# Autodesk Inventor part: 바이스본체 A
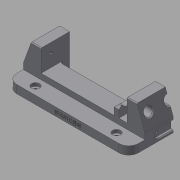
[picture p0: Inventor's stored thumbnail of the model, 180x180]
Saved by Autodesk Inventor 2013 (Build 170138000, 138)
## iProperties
Created: 2017-04
Part Number: 바이스본체 A
Material: 일반
Document SubType Name: Modeling
Designer: mduedu
Density: 1 g/cm^3
Mass: 119.631 g
Surface Area: 276.734 cm^2
Volume: 119.631 cm^3
Author: mduedu
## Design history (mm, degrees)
sketch "스케치1"
  geometry: L1 (-75, 0)-(75, 0); L2 (-75, 0)-(-75, 17); L3 (-53, 17)-(53, 17); L4 (75, 17)-(75, 0); L5 (-75, 17)-(-65.173, 44); L6 (-65.173, 44)-(-53, 44); L7 (-53, 44)-(-53, 17); L8 (0, 0)-(0, 17); L9 (75, 17)-(65.173, 44); L10 (65.173, 44)-(53, 44); L11 (53, 44)-(53, 17); 1 further point
  constraints: 22 end point, 4 perpendicular, 2 horizontal alignment, 2 midpoint, 2 symmetric about line, 1 coincident, 1 collinear, 1 horizontal, 1 vertical
  dimensions: "d0" = 150 distance of L1.start L1.end; "d1" = 17 distance of L1.start L2.end; "d2" = 27 distance of L3.start L6.end; "d3" = 22 distance of L3.start L2.end; "d4" = 70 deg angle of L3 L5; "d54" = 20 deg angle of L9 L4
extrude "돌출1" new body sketch "스케치1" stored distance "d5" = 70; taper "d6" = 0 deg
sketch "스케치2"
  geometry: L1 (0, 70)-(106, 70) reference; L2 (106, 70)-(106, 0) reference; L3 (106, 0)-(0, 0) reference; L4 (0, 47)-(106, 47); L5 (106, 47)-(106, 23); L6 (106, 23)-(0, 23); L7 (0, 23)-(0, 47); L8 (0, 70)-(0, 0) reference; 2 further points
  constraints: 8 end point, 2 parallel, 2 point on line, 1 horizontal, 1 horizontal alignment, 1 midpoint, 1 perpendicular
  dimensions: "d7" = 24 distance between parallel lines of L6 L4
extrude "돌출2" cut sketch "스케치2" stored distance "d9" = 70; taper "d10" = 0 deg
sketch "스케치3"
  geometry: L1 (22, -23)-(128, -23) reference; L2 (128, -47)-(22, -47) reference; L3 (22, -18)-(128, -18); L4 (128, -52)-(22, -52); L5 (22, -18)-(22, -52); L6 (128, -18)-(128, -52); 1 further point
  constraints: 8 end point, 3 parallel, 2 point on line, 1 perpendicular
  dimensions: "d11" = 5 distance between parallel lines of L3 L1; "d12" = 5 distance between parallel lines of L4 L2
extrude "돌출3" cut sketch "스케치3" distance "d13" = 12; taper "d14" = 0 deg
fillet "모깎기1" dims "d15" = 3, "d16" = 3
sketch "스케치4"
  geometry: L1 (103, 23)-(3, 23) reference; L2 (0, 26)-(0, 0) reference; L3 (106, 0)-(0, 0) reference; L4 (106, 26)-(106, 0) reference; L5 (96, 0)-(90, 0); L6 (90, 0)-(90, 19.5); L7 (96, 19.5)-(96, 0); L8 (90, 19.5)-(96, 19.5); A1 r 3 centre (3, 26) between (0, 26) and (3, 23) reference; A2 r 3 centre (103, 26) between (103, 23) and (106, 26) reference; 1 further point
  constraints: 8 end point, 2 perpendicular, 1 horizontal, 1 parallel, 1 point on line
  dimensions: "d17" = 10 distance between parallel lines of L7 L4; "d18" = 6 distance between parallel lines of L7 L6; "d27" = 3.5 distance between parallel lines of L8 L1
extrude "돌출4" join sketch "스케치4" distance "d19" = 12; taper "d20" = 0 deg
chamfer "모따기1" distance "d21" = 3; stored, may be unused: second distance "d22" = 2, angle "d23" = 45 deg
chamfer "모따기2" distance "d24" = 3; stored, may be unused: second distance "d25" = 2, angle "d26" = 45 deg
sketch "스케치5"
  geometry: L1 (-15.5, 35.8)-(-15.5, -25.8) reference; L2 (19.5, 0)-(0, 0) reference; C1 r 6.5 at (9.5, 15); 1 further point
  constraints: 1 centre point
  dimensions: "d28" = 13 diameter of C1; "d30" = 15 distance from line of C1.centre L2; "d31" = 25 distance from line of C1.centre L1
extrude "돌출5" cut sketch "스케치5" stored distance "d32" = 12; taper "d33" = 0 deg
sketch "스케치6"
  geometry: C1 r 5 at (-10, 15); C2 r 5 at (-60, 15); A1 r 6.5 centre (-10, 15) between (-15.766, 12) and (-4.234, 12) reference; A2 r 6.5 centre (-60, 15) between (-65.766, 12) and (-54.234, 12) reference; 1 further point
  constraints: 2 centre point, 2 coincident
  dimensions: "d34" = 10 diameter of C1; "d35" = 10 diameter of C2 (= d34)
extrude "돌출6" cut sketch "스케치6" stored distance "d36" = 12; taper "d37" = 0 deg
chamfer "모따기3" distance "d38" = 1; stored, may be unused: second distance "d39" = 2, angle "d40" = 45 deg
chamfer "모따기4" distance "d41" = 1; stored, may be unused: second distance "d42" = 2, angle "d43" = 45 deg
sketch "스케치7"
  geometry: L1 (-35, 35.8)-(-35, -25.8) reference; L2 (-70, 0)-(0, 0) reference; C1 r 5 at (-35, 15); 1 further point
  constraints: 1 centre point, 1 point on line
  dimensions: "d44" = 10 diameter of C1; "d45" = 15 distance from line of C1.centre L2
extrude "돌출7" cut sketch "스케치7" stored distance "d46" = 12; taper "d47" = 0 deg
chamfer "모따기5" distance "d48" = 1; stored, may be unused: second distance "d49" = 2, angle "d50" = 45 deg
node "작업축1"
sketch "스케치8"
  geometry: L1 (-105, 32)-(105, 32) reference; L2 (58, 32)-(64, 32); L3 (64, 32)-(64, 40); L4 (64, 40)-(58, 40); L5 (58, 40)-(58, 32); L6 (53, 38)-(53, 26) reference; 1 further point
  constraints: 8 end point, 2 parallel, 1 horizontal, 1 perpendicular, 1 point on line
  dimensions: "d51" = 5 distance from line of L6 L2.start; "d52" = 6 distance of L3.end L4.end; "d53" = 16 diameter of L4 L1
revolve "회전1" sketch "스케치8" stored, may be unused: angle "d55" = 90 deg
fillet "모깎기2"
chamfer "모따기6" distance "d56" = 1; stored, may be unused: second distance "d57" = 2, angle "d58" = 45 deg
sketch "스케치9"
  geometry: L1 (17.5, 3)-(52.5, 3); L2 (52.5, 13)-(17.5, 13); L3 (70, 0)-(0, 0) reference; L4 (17.5, 8)-(52.5, 8); A1 r 5 centre (17.5, 8) between (17.5, 13) and (17.5, 3); A2 r 5 centre (52.5, 8) between (52.5, 3) and (52.5, 13); 3 further points
  constraints: 6 end point, 4 point on circle, 3 tangent, 2 centre point, 2 midpoint, 2 parallel, 1 horizontal, 1 vertical alignment
  dimensions: "d59" = 35 distance of L4.start L4.end; "d61" = 5 radius of A2; "d62" = 8 distance between parallel lines of L3 L4
extrude "돌출8" cut sketch "스케치9" distance "d63" = 3; taper "d64" = 0 deg
chamfer "모따기7" distance "d65" = 1; stored, may be unused: second distance "d66" = 2, angle "d67" = 45 deg
chamfer "모따기8" distance "d68" = 1; stored, may be unused: second distance "d69" = 2, angle "d70" = 45 deg
feature "분할1"
sketch "스케치10"
  geometry: L1 (35, 27)-(0, 27) reference; L2 (0, 0)-(0, 27) reference; 1 further point
  dimensions: "d85" = 11.5 distance from line of point (12, 15.5) L1; "d86" = 12 distance from line of point (12, 15.5) L2
hole "구멍1" sketch "스케치10" at (12, 15.5) diameter "d71" = 3.242; stored, may be unused: countersink angle "d75" = 90 deg, drill point angle "d77" = 120 deg; dims "d72" = 6, "d73" = 4, "d74" = 2, "d76" = 8
sketch "스케치11"
  geometry: A1 r 5 centre (17.5, 8) between (17.5, 13) and (17.5, 3) reference; 1 further point
  constraints: 1 coincident
hole "구멍3" sketch "스케치11" at (17.5, 8) diameter "d78" = 2.459; stored, may be unused: countersink angle "d82" = 90 deg, drill point angle "d84" = 120 deg; dims "d79" = 4.5, "d80" = 4, "d81" = 2, "d83" = 6
sketch "스케치13"
  geometry: L1 (75, 0)-(75, 35) reference; L2 (-75, 0)-(-75, 35) reference; L3 (-75, 35)-(75, 35); L4 (75, 35)-(75, 55); L5 (75, 55)-(-75, 55); L6 (-75, 55)-(-75, 35); 1 further point
  constraints: 8 end point, 2 parallel, 1 horizontal, 1 perpendicular, 1 point on line
  dimensions: "d90" = 20 distance between parallel lines of L5 L3; "d94" = 150 distance of L4.end L5.end (derived)
extrude "돌출9" join sketch "스케치13" distance "d92" = 10; taper "d93" = 0 deg
sketch "스케치14"
  geometry: L1 (-75, -35)-(-75, -55) reference; L2 (75, -55)-(75, -35) reference; L3 (-75, -45)-(75, -45); 3 further points
  constraints: 2 end point, 2 midpoint, 2 point on line
  dimensions: "d95" = 50 horizontal distance of point (-50, -45) point (0, 0); "d96" = 100 distance of point (50, -45) point (-50, -45)
fillet "모깎기3" dims "d97" = 12
chamfer "모따기9" distance "d98" = 1; stored, may be unused: second distance "d99" = 2, angle "d100" = 45 deg
hole "구멍4" sketch "스케치14" diameter "d101" = 4.134; stored, may be unused: countersink angle "d105" = 90 deg, drill point angle "d107" = 118 deg; dims "d102" = 6, "d103" = 10, "d104" = 4, "d106" = 8
sketch "스케치15"
  geometry: L1 (0, 0)-(126, 0) reference; 3 further points
  constraints: 1 midpoint, 1 vertical alignment, 1 other
  dimensions: "d109" = 5 distance from line of point (63, 5) L1
feature "엠보싱2" sketch "스케치15" dims "d0" = 150, "d1" = 17, "d2" = 27, "d3" = 22, "d4" = 70 deg, "d54" = 20 deg, "d110" = 0.5, "d111" = 0
node "솔리드1"
mirror "대칭1"
mirror "대칭2"
mirror "대칭3"
mirror "대칭4"
node "투영된 루프1"
